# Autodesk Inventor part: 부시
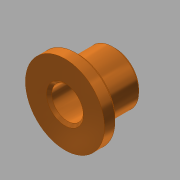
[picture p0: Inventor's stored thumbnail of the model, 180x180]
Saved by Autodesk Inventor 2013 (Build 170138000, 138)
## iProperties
Created: 2016-02
Part Number: 부시
Material: 스테인리스강
Document SubType Name: Modeling
Designer: mduedu
Density: 8.08 g/cm^3
Mass: 45.9536 g
Surface Area: 31.3929 cm^2
Volume: 5.68733 cm^3
Author: mduedu
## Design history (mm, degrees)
sketch "스케치1"
  geometry: C1 r 15 at (0, 0); 1 further point
  constraints: 1 centre point, 1 coincident
  dimensions: "d0" = 30 diameter of C1
extrude "돌출1" new body sketch "스케치1" distance "d1" = 5; taper "d2" = 0 deg
sketch "스케치2"
  geometry: C1 r 10 at (0, 0); 1 further point
  constraints: 1 centre point, 1 coincident
  dimensions: "d3" = 20 diameter of C1
extrude "돌출2" join sketch "스케치2" distance "d4" = 14; taper "d5" = 0 deg
hole "구멍1" diameter "d8" = 12; stored, may be unused: countersink angle "d12" = 90 deg, drill point angle "d14" = 118 deg; dims "d9" = 6, "d10" = 4, "d11" = 2, "d13" = 8, "d15" = 10, "d16" = 10
chamfer "모따기1" distance "d17" = 1; stored, may be unused: second distance "d18" = 2, angle "d19" = 45 deg
chamfer "모따기2" distance "d20" = 1; stored, may be unused: second distance "d21" = 2, angle "d22" = 45 deg
chamfer "모따기3" distance "d23" = 1; stored, may be unused: second distance "d24" = 2, angle "d25" = 45 deg
node "솔리드1"
